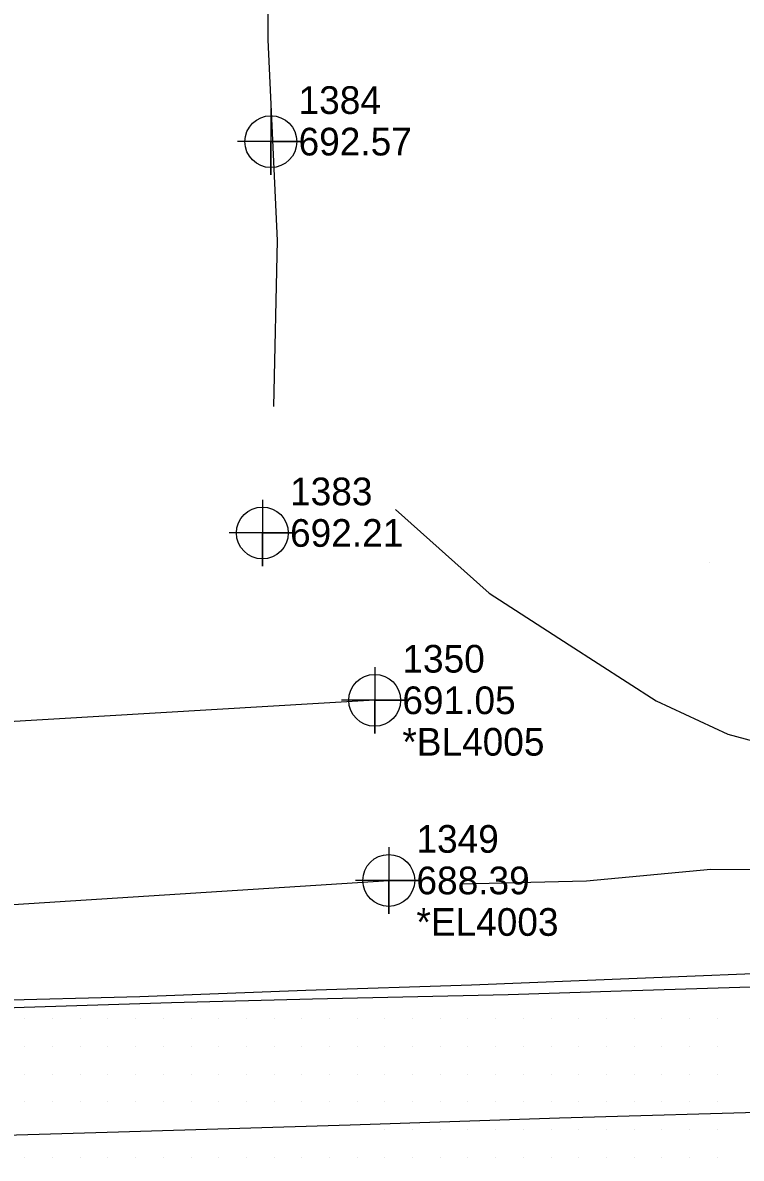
# Model space of a CAD drawing. Extents: x 1755643 to 1760494, y 736519 to 737621.
# Drawn here: x 1759143.6 to 1759208.4, y 737021.1 to 737123.7 of the extents above; entities that cross this region are included whole.
import ezdxf

# ---------------------------------------------------------------- set-up
doc = ezdxf.new("R2010")
doc.units = 0
for name, color, linetype in [('Exist Horizontal Alignment Curve and Spiral Data', 7, 'Continuous'), ('Exist Horizontal Alignment Direction Label', 7, 'Continuous'), ('Exist Railroads Standard Gauge', 7, 'Continuous'), ('Exist Roads EOT', 7, 'Continuous'), ('Old_Level_1', 7, 'Continuous'), ('Old_Level_10', 7, 'Continuous'), ('Old_Level_2', 7, 'Continuous'), ('Old_Level_3', 7, 'Continuous'), ('Prop Dimension', 7, 'Continuous'), ('Prop EOT Dash', 7, 'Continuous'), ('Prop Horizontal Alignment Direction Label', 7, 'Continuous'), ('Prop Lane Lines', 7, 'Continuous'), ('Prop Paint Stripe', 7, 'Continuous'), ('Prop Paved Shoulder', 7, 'Continuous'), ('Scratch_Level_1', 7, 'Continuous'), ('Scratch_Level_2', 7, 'Continuous'), ('Scratch_Level_5', 7, 'Continuous'), ('Scratch_Level_9', 7, 'Continuous')]:
    doc.layers.add(name, color=color, linetype=linetype)

msp = doc.modelspace()

# ---------------------------------------------------------------- linework, layer by layer
at = {"layer": 'Exist Horizontal Alignment Curve and Spiral Data'}
for points in [[(1759165.96, 737115.96), (1759165.96, 737109.96), (1759165.96, 737112.96), (1759168.96, 737112.96), (1759162.96, 737112.96)], [(1759165.19, 737080.62), (1759165.19, 737074.62), (1759165.19, 737077.62), (1759168.19, 737077.62), (1759162.19, 737077.62)]]:
    msp.add_lwpolyline(points, dxfattribs=at)
for centre in [(1759165.96, 737112.96), (1759165.19, 737077.62)]:
    msp.add_circle(centre, 2.34, dxfattribs=at)
at = {"layer": 'Exist Railroads Standard Gauge'}
for points in [[(1759166.23, 737089.04), (1759166.56, 737104.02), (1759165.73, 737122.15), (1759165.69, 737132.45), (1759165.81, 737135.36), (1759176, 737135.12), (1759181.45, 737135.1), (1759195.95, 737135.05), (1759204.48, 737135.24)], [(1759177.21, 737079.73), (1759185.66, 737072.19), (1759192.9, 737067.53), (1759200.73, 737062.46), (1759207.2, 737059.46), (1759213.93, 737057.65), (1759223.26, 737057.71), (1759232.91, 737057.84), (1759238.36, 737055.52), (1759243.57, 737052.23), (1759247.64, 737048.67), (1759248.31, 737045.86), (1759244.98, 737044.5), (1759241.87, 737047.01), (1759232.4, 737047.04), (1759215.81, 737047.19), (1759205.67, 737047.23), (1759194.46, 737046.19), (1759183.13, 737045.89)]]:
    msp.add_lwpolyline(points, dxfattribs=at)
at = {"layer": 'Old_Level_10'}
msp.add_lwpolyline([(1759176.6, 737049.24), (1759176.6, 737043.24), (1759176.6, 737046.24), (1759179.6, 737046.24), (1759173.6, 737046.24)], dxfattribs=at)
msp.add_circle((1759176.6, 737046.24), 2.34, dxfattribs=at)
at = {"layer": 'Prop Dimension'}
msp.add_line((1759128.19, 737043.12), (1759176.6, 737046.24), dxfattribs=at)
at = {"layer": 'Prop Lane Lines'}
msp.add_lwpolyline([(1759175.33, 737065.51), (1759175.33, 737059.51), (1759175.33, 737062.51), (1759178.33, 737062.51), (1759172.33, 737062.51)], dxfattribs=at)
msp.add_circle((1759175.33, 737062.51), 2.34, dxfattribs=at)
at = {"layer": 'Prop Paint Stripe'}
msp.add_line((1759205.53, 737074.99), (1759205.53, 737074.99), dxfattribs=at)
at = {"layer": 'Scratch_Level_1'}
msp.add_lwpolyline([(1759245.74, 737039.35), (1759243.9, 737039.09), (1759228.95, 737038.55), (1759213.99, 737037.99), (1759199.03, 737037.38), (1759184.08, 737036.79), (1759169.11, 737036.29), (1759154.14, 737035.74), (1759140.16, 737035.36), (1759125.18, 737034.91), (1759110.19, 737034.39), (1759095.21, 737033.87), (1759083.32, 737033.73), (1759067.8, 737033.62), (1759060.8, 737033.37)], dxfattribs=at)
at = {"layer": 'Scratch_Level_2'}
for p, q in [((1759143.75, 737033.75), (1759143.75, 737033.75)), ((1759146.25, 737033.75), (1759146.25, 737033.75)), ((1759148.75, 737033.75), (1759148.75, 737033.75)), ((1759151.25, 737033.75), (1759151.25, 737033.75)), ((1759153.75, 737033.75), (1759153.75, 737033.75)), ((1759156.25, 737033.75), (1759156.25, 737033.75)), ((1759158.75, 737033.75), (1759158.75, 737033.75)), ((1759161.25, 737033.75), (1759161.25, 737033.75)), ((1759163.75, 737033.75), (1759163.75, 737033.75)), ((1759166.25, 737033.75), (1759166.25, 737033.75)), ((1759168.75, 737033.75), (1759168.75, 737033.75)), ((1759171.25, 737033.75), (1759171.25, 737033.75)), ((1759173.75, 737033.75), (1759173.75, 737033.75)), ((1759176.25, 737033.75), (1759176.25, 737033.75)), ((1759178.75, 737033.75), (1759178.75, 737033.75)), ((1759181.25, 737033.75), (1759181.25, 737033.75)), ((1759183.75, 737033.75), (1759183.75, 737033.75)), ((1759186.25, 737033.75), (1759186.25, 737033.75)), ((1759188.75, 737033.75), (1759188.75, 737033.75)), ((1759191.25, 737033.75), (1759191.25, 737033.75)), ((1759193.75, 737033.75), (1759193.75, 737033.75)), ((1759196.25, 737033.75), (1759196.25, 737033.75)), ((1759198.75, 737033.75), (1759198.75, 737033.75)), ((1759201.25, 737033.75), (1759201.25, 737033.75)), ((1759203.75, 737033.75), (1759203.75, 737033.75)), ((1759206.25, 737033.75), (1759206.25, 737033.75)), ((1759143.75, 737031.25), (1759143.75, 737031.25)), ((1759146.25, 737031.25), (1759146.25, 737031.25)), ((1759148.75, 737031.25), (1759148.75, 737031.25)), ((1759151.25, 737031.25), (1759151.25, 737031.25)), ((1759153.75, 737031.25), (1759153.75, 737031.25)), ((1759156.25, 737031.25), (1759156.25, 737031.25)), ((1759158.75, 737031.25), (1759158.75, 737031.25)), ((1759161.25, 737031.25), (1759161.25, 737031.25)), ((1759163.75, 737031.25), (1759163.75, 737031.25)), ((1759166.25, 737031.25), (1759166.25, 737031.25)), ((1759168.75, 737031.25), (1759168.75, 737031.25)), ((1759171.25, 737031.25), (1759171.25, 737031.25)), ((1759173.75, 737031.25), (1759173.75, 737031.25)), ((1759176.25, 737031.25), (1759176.25, 737031.25)), ((1759178.75, 737031.25), (1759178.75, 737031.25)), ((1759181.25, 737031.25), (1759181.25, 737031.25)), ((1759183.75, 737031.25), (1759183.75, 737031.25)), ((1759186.25, 737031.25), (1759186.25, 737031.25)), ((1759188.75, 737031.25), (1759188.75, 737031.25)), ((1759191.25, 737031.25), (1759191.25, 737031.25)), ((1759193.75, 737031.25), (1759193.75, 737031.25)), ((1759196.25, 737031.25), (1759196.25, 737031.25)), ((1759198.75, 737031.25), (1759198.75, 737031.25)), ((1759201.25, 737031.25), (1759201.25, 737031.25)), ((1759203.75, 737031.25), (1759203.75, 737031.25)), ((1759206.25, 737031.25), (1759206.25, 737031.25)), ((1759143.75, 737028.75), (1759143.75, 737028.75)), ((1759146.25, 737028.75), (1759146.25, 737028.75)), ((1759148.75, 737028.75), (1759148.75, 737028.75)), ((1759151.25, 737028.75), (1759151.25, 737028.75)), ((1759153.75, 737028.75), (1759153.75, 737028.75)), ((1759156.25, 737028.75), (1759156.25, 737028.75)), ((1759158.75, 737028.75), (1759158.75, 737028.75)), ((1759161.25, 737028.75), (1759161.25, 737028.75)), ((1759163.75, 737028.75), (1759163.75, 737028.75)), ((1759166.25, 737028.75), (1759166.25, 737028.75)), ((1759168.75, 737028.75), (1759168.75, 737028.75)), ((1759171.25, 737028.75), (1759171.25, 737028.75)), ((1759173.75, 737028.75), (1759173.75, 737028.75)), ((1759176.25, 737028.75), (1759176.25, 737028.75)), ((1759178.75, 737028.75), (1759178.75, 737028.75)), ((1759181.25, 737028.75), (1759181.25, 737028.75)), ((1759183.75, 737028.75), (1759183.75, 737028.75)), ((1759186.25, 737028.75), (1759186.25, 737028.75)), ((1759188.75, 737028.75), (1759188.75, 737028.75)), ((1759191.25, 737028.75), (1759191.25, 737028.75)), ((1759193.75, 737028.75), (1759193.75, 737028.75)), ((1759196.25, 737028.75), (1759196.25, 737028.75)), ((1759198.75, 737028.75), (1759198.75, 737028.75)), ((1759201.25, 737028.75), (1759201.25, 737028.75)), ((1759203.75, 737028.75), (1759203.75, 737028.75)), ((1759206.25, 737028.75), (1759206.25, 737028.75)), ((1759143.75, 737026.25), (1759143.75, 737026.25)), ((1759146.25, 737026.25), (1759146.25, 737026.25)), ((1759148.75, 737026.25), (1759148.75, 737026.25)), ((1759151.25, 737026.25), (1759151.25, 737026.25)), ((1759153.75, 737026.25), (1759153.75, 737026.25)), ((1759156.25, 737026.25), (1759156.25, 737026.25)), ((1759158.75, 737026.25), (1759158.75, 737026.25)), ((1759161.25, 737026.25), (1759161.25, 737026.25)), ((1759163.75, 737026.25), (1759163.75, 737026.25)), ((1759166.25, 737026.25), (1759166.25, 737026.25)), ((1759168.75, 737026.25), (1759168.75, 737026.25)), ((1759171.25, 737026.25), (1759171.25, 737026.25)), ((1759173.75, 737026.25), (1759173.75, 737026.25)), ((1759176.25, 737026.25), (1759176.25, 737026.25)), ((1759178.75, 737026.25), (1759178.75, 737026.25)), ((1759181.25, 737026.25), (1759181.25, 737026.25)), ((1759183.75, 737026.25), (1759183.75, 737026.25)), ((1759186.25, 737026.25), (1759186.25, 737026.25)), ((1759188.75, 737026.25), (1759188.75, 737026.25)), ((1759191.25, 737026.25), (1759191.25, 737026.25)), ((1759193.75, 737026.25), (1759193.75, 737026.25)), ((1759196.25, 737026.25), (1759196.25, 737026.25)), ((1759198.75, 737026.25), (1759198.75, 737026.25)), ((1759201.25, 737026.25), (1759201.25, 737026.25)), ((1759203.75, 737026.25), (1759203.75, 737026.25)), ((1759206.25, 737026.25), (1759206.25, 737026.25)), ((1759176.25, 737023.75), (1759176.25, 737023.75)), ((1759178.75, 737023.75), (1759178.75, 737023.75)), ((1759181.25, 737023.75), (1759181.25, 737023.75)), ((1759183.75, 737023.75), (1759183.75, 737023.75)), ((1759186.25, 737023.75), (1759186.25, 737023.75)), ((1759188.75, 737023.75), (1759188.75, 737023.75)), ((1759191.25, 737023.75), (1759191.25, 737023.75)), ((1759193.75, 737023.75), (1759193.75, 737023.75)), ((1759196.25, 737023.75), (1759196.25, 737023.75)), ((1759198.75, 737023.75), (1759198.75, 737023.75)), ((1759201.25, 737023.75), (1759201.25, 737023.75)), ((1759203.75, 737023.75), (1759203.75, 737023.75)), ((1759206.25, 737023.75), (1759206.25, 737023.75)), ((1759143.75, 737021.25), (1759143.75, 737021.25)), ((1759146.25, 737021.25), (1759146.25, 737021.25)), ((1759148.75, 737021.25), (1759148.75, 737021.25)), ((1759151.25, 737021.25), (1759151.25, 737021.25)), ((1759153.75, 737021.25), (1759153.75, 737021.25)), ((1759156.25, 737021.25), (1759156.25, 737021.25)), ((1759158.75, 737021.25), (1759158.75, 737021.25)), ((1759161.25, 737021.25), (1759161.25, 737021.25)), ((1759163.75, 737021.25), (1759163.75, 737021.25)), ((1759166.25, 737021.25), (1759166.25, 737021.25)), ((1759168.75, 737021.25), (1759168.75, 737021.25)), ((1759171.25, 737021.25), (1759171.25, 737021.25)), ((1759173.75, 737021.25), (1759173.75, 737021.25)), ((1759176.25, 737021.25), (1759176.25, 737021.25)), ((1759178.75, 737021.25), (1759178.75, 737021.25)), ((1759181.25, 737021.25), (1759181.25, 737021.25)), ((1759183.75, 737021.25), (1759183.75, 737021.25)), ((1759186.25, 737021.25), (1759186.25, 737021.25)), ((1759188.75, 737021.25), (1759188.75, 737021.25)), ((1759191.25, 737021.25), (1759191.25, 737021.25)), ((1759193.75, 737021.25), (1759193.75, 737021.25)), ((1759196.25, 737021.25), (1759196.25, 737021.25)), ((1759198.75, 737021.25), (1759198.75, 737021.25)), ((1759201.25, 737021.25), (1759201.25, 737021.25)), ((1759203.75, 737021.25), (1759203.75, 737021.25)), ((1759206.25, 737021.25), (1759206.25, 737021.25))]:
    msp.add_line(p, q, dxfattribs=at)
at = {"layer": 'Scratch_Level_5'}
for points in [[(1759264.35, 737038.16), (1759256.26, 737037.9), (1759245.17, 737037.58), (1759230.48, 737037.15), (1759220.48, 737036.89), (1759208.3, 737036.58), (1759197.58, 737036.23), (1759187.39, 737035.92), (1759169.71, 737035.52), (1759156.99, 737035.18), (1759143.7, 737034.76), (1759131.38, 737034.35), (1759120.36, 737034.07), (1759107.28, 737033.59), (1759090.93, 737033.18), (1759076.25, 737032.7), (1759069.72, 737032.56)], [(1759069.6, 737021.15), (1759087.67, 737021.69), (1759105.38, 737022.11), (1759116.56, 737022.49), (1759127.59, 737022.81), (1759137.85, 737023.13), (1759152.2, 737023.55), (1759173.12, 737024.16), (1759192.02, 737024.81), (1759212.99, 737025.41), (1759241.37, 737026.25), (1759257.05, 737026.72), (1759264.84, 737026.96)]]:
    msp.add_lwpolyline(points, dxfattribs=at)
at = {"layer": 'Scratch_Level_9'}
msp.add_line((1759175.33, 737062.51), (1759121.45, 737059.32), dxfattribs=at)

# ---------------------------------------------------------------- texts
at = {"layer": 'Exist Horizontal Alignment Direction Label'}
msp.add_text('*BL4005', height=2.5, dxfattribs=at).set_placement((1759177.83, 737057.51))
at = {"layer": 'Exist Roads EOT'}
for s, p in [('1384', (1759168.46, 737115.46)), ('1383', (1759167.69, 737080.12))]:
    msp.add_text(s, height=2.5, dxfattribs=at).set_placement(p)
at = {"layer": 'Old_Level_1'}
msp.add_text('1349', height=2.5, dxfattribs=at).set_placement((1759179.1, 737048.74))
at = {"layer": 'Old_Level_2'}
msp.add_text('688.39', height=2.5, dxfattribs=at).set_placement((1759179.1, 737044.99))
at = {"layer": 'Old_Level_3'}
msp.add_text('691.05', height=2.5, dxfattribs=at).set_placement((1759177.83, 737061.26))
at = {"layer": 'Prop EOT Dash'}
msp.add_text('1350', height=2.5, dxfattribs=at).set_placement((1759177.83, 737065.01))
at = {"layer": 'Prop Horizontal Alignment Direction Label'}
msp.add_text('*EL4003', height=2.5, dxfattribs=at).set_placement((1759179.1, 737041.24))
at = {"layer": 'Prop Paved Shoulder'}
for s, p in [('692.57', (1759168.46, 737111.71)), ('692.21', (1759167.69, 737076.37))]:
    msp.add_text(s, height=2.5, dxfattribs=at).set_placement(p)

doc.saveas('drawing.dxf')
